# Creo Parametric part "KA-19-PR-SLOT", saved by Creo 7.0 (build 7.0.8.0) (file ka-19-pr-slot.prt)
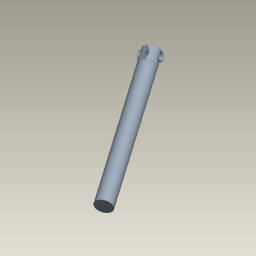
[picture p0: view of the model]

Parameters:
  PTC_COMMON_NAME = "ka-19-pr-slot.prt"
  PTC_WM_REVISION = "A"
  PTC_WM_ITERATION = "1"
  PTC_WM_VERSION = "A.1"
  PTC_WM_LIFECYCLE_STATE = "Concept"
  PTC_WM_LIFECYCLE = "Life Cycle Schema Type 1"
  PTC_WM_LOCATION = "/Products/KA19_CN2215/CAD"
  PTC_WM_CREATED_BY = "Jörg Monien"
  PTC_WM_CREATED_ON = "2026-08-11"
  PTC_WM_MODIFIED_BY = "Jörg Monien"
  PTC_WM_MODIFIED_ON = "2026-08-11"
  PTC_WM_NAME = "ka-19-pr-slot.prt"
  PTC_WM_NUMBER = "KA-19-PR-SLOT.PRT"
  PDMREV = "A.1+"
  PDMRL = "Concept"
  PROI_REVISION = "A"
  PROI_VERSION = "1"
  PROI_RELEASE = "Concept"

Created from: 1079W4001-PR-MS.PRT

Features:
  1. datum plane "RIGHT"
  2. datum plane "TOP"
  3. datum plane "FRONT"
  4. coordinate system
  5. datum axis
  6. datum axis
  7. datum axis
  8. imported feature
  9. imported feature "Import Feature id 2574"
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
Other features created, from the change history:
  datum plane "DTM2" (2 times)
  mirror "Mirror 1"

Other named items: X-AXES, Y-AXES, Z-AXES, X-AXES_1, B, Z-AXES_1, CS0, CS0_1, WO-BUSHING

Layers: ANNOTATIONS, AXES, COSMETICS, CSYS, CURVES, EXT_COPY_GEOM, PLANES, POINTS, PUBLISHED_GEOM, QUILTS, SOLIDS, STARTUP

Notes: NOT SPECIFIED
